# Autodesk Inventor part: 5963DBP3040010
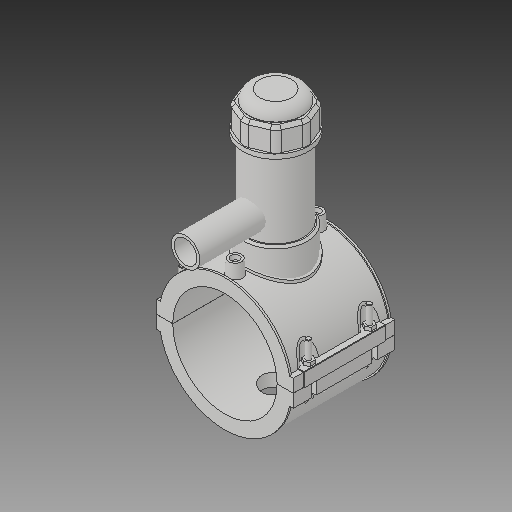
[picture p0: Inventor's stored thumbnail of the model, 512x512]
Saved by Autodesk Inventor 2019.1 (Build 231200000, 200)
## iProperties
Created: 2017-07
Part Number: 5963DBP3040010
Material: Generic
Description: PLASSON TAPPING SADDLE 4''DIPS x 1''IPS
Document SubType Name: Modeling
Designer: KIM
Density: 1 g/cm^3
Appearance: Default
Author: KIM
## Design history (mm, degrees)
derived "5963DBP_5963BUP.ipt"
feature "Solid1::5963DBP_5963BUP.ipt"
feature "Solid2::5963DBP_5963BUP.ipt"
feature "Solid3::5963DBP_5963BUP.ipt"
tag "TaggingFeature1"
body "Solid1"
body "Solid2"
body "Solid3"
other parameters: "d0" = 121.3, "d2" = 159.004, "d3" = 30.325, "d4" = 118.11, "d5" = 0, "d6" = 0.1, "d8" = 0, "d19" = 6, "d20" = 6, "d21" = 70.866, "d23" = 0, "d24" = 35.433, "d26" = 0, "d27" = 3, "d28" = 3, "d29" = 3, "d30" = 40.43333, "d31" = 6, "d32" = 0, "d33" = 0, "d34" = 0.6, "d40" = 78.21424, "d41" = 76.419, "d43" = 0, "d45" = 0, "d47" = 146.072, "d70" = 15, "d72" = 0, "d73" = 6, "d75" = 5, "d76" = 0, "d77" = 6.065, "d78" = 90.65, "d79" = 15, "d80" = 47.244, "d82" = 5 deg, "d84" = 4, "d85" = 14, "d86" = 0, "d87" = 3, "d88" = 0, "d89" = 1, "d90" = 1, "d91" = 94.488, "d92" = 0, "d93" = 0.5, "d94" = 63.84211, "d96" = 153.42024, "d97" = 2.3622, "d98" = 0, "d120" = 140 deg, "d121" = 24.228, "d122" = 20 deg, "d123" = 300.824, "d124" = 90.2472, "d126" = 0, "d143" = 124.939, "d145" = 22.39385, "d149" = 1.8195, "d150" = 24.63323, "d153" = 118.11, "d154" = 0, "d156" = 75.206, "d157" = 160 deg, "d159" = 5.8224, "d161" = 1.8195, "d162" = 70.866, "d163" = 0, "d164" = 60.65, "d167" = 12.13, "d168" = 73.37171, "d170" = 3.4335, "d172" = 0, "d173" = 1, "d175" = 60.65, "d176" = 20 deg, "d177" = 8.491, "d178" = 29.112, "d180" = 0, "d183" = 11.6448, "d184" = 6.7928, "d185" = 38.38575, "d186" = 38.38575, "d187" = 75.206, "d188" = 8.7336, "d189" = 8.491, "d190" = 0, "d191" = 112.809, "d193" = 7.3248, "d194" = 4.13385, "d195" = 90 deg, "d197" = 0, "d199" = 0, "d200" = 14.556, "d202" = 0, "d203" = 177.038, "d204" = 72.59805, "d205" = 53.4933, "d206" = 64.95615, "d207" = 132.7785, "d208" = 138.08964, "d209" = 164.64534, "d210" = 65.72034, "d211" = 76.419, "d212" = 61.1352, "d213" = 43.5366, "d216" = 0, "d217" = 12.13, "d218" = 12.13, "d219" = 2.426, "d222" = 121.3, "d224" = 0, "d225" = 65.024, "d226" = 33.3, "d227" = 26.64, "d228" = 104.902, "d230" = 3.639, "d_" = 121.3, "B_" = 159.004, "L_" = 118.11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
